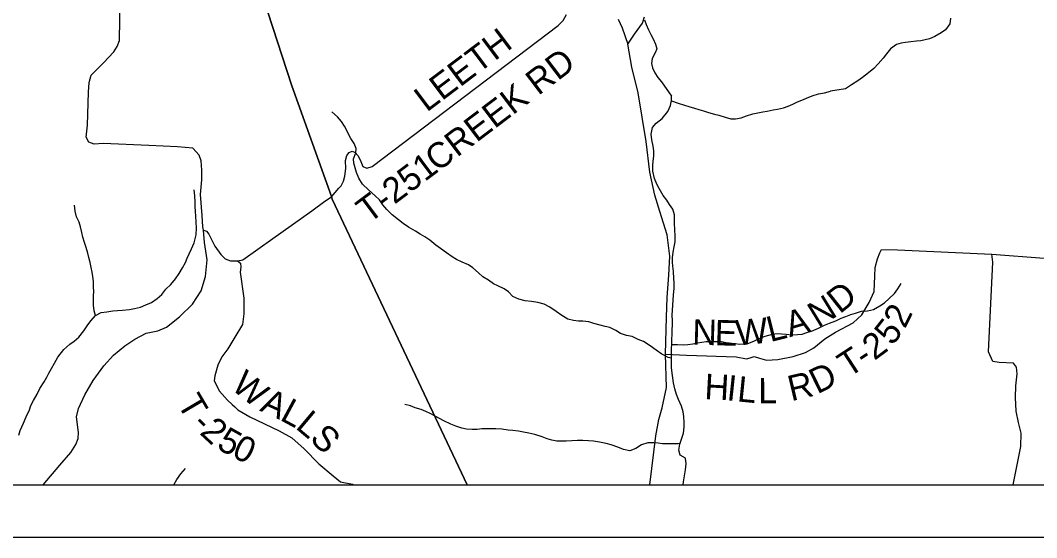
# Model space of a CAD drawing. Extents: x 0 to 34, y 0 to 22.
# Drawn here: x 3.486 to 5.759, y 13.882 to 15.038 of the extents above; entities that cross this region are included whole.
import ezdxf

# ---------------------------------------------------------------- set-up
doc = ezdxf.new("R2010")
doc.units = 0
for name, color, linetype in [('Default', 7, 'Continuous'), ('GM_X_County_Road', 7, 'Continuous'), ('GM_X_Minor_River', 7, 'Continuous'), ('GM_X_Township_Road', 7, 'Continuous'), ('GM_X_Township_Road_Text', 7, 'Continuous'), ('SH_Cut_Line', 7, 'Continuous')]:
    doc.layers.add(name, color=color, linetype=linetype)

msp = doc.modelspace()

# ---------------------------------------------------------------- linework, layer by layer
at = {"layer": 'Default'}
msp.add_lwpolyline([(9.087, 13.8822), (2.1062, 13.8822), (2.1062, 20.9054), (9.087, 20.9054)], close=True, dxfattribs=at)
for points in [[(2.2, 14), (4.485, 14), (4.1837, 14.6383), (4.1816, 14.6445), (4.0933, 14.8918), (3.8786, 15.5505)], [(3.8786, 15.5505), (4.0933, 14.8918), (4.1816, 14.6445), (4.1837, 14.6383), (4.485, 14), (9, 14)]]:
    msp.add_lwpolyline(points, dxfattribs=at)
at = {"layer": 'GM_X_County_Road'}
for points in [[(3.5373, 14), (3.5742, 14.0443), (3.5988, 14.0725), (3.6104, 14.0906), (3.6151, 14.1035), (3.616, 14.1168), (3.6118, 14.1522), (3.6165, 14.1711), (3.6301, 14.2014), (3.6487, 14.2335), (3.6725, 14.2659), (3.6944, 14.2899), (3.7196, 14.3106), (3.7425, 14.3259), (3.7677, 14.3389), (3.7939, 14.3443), (3.8133, 14.3524), (3.842, 14.3757), (3.8711, 14.4042), (3.8904, 14.434), (3.8998, 14.4658), (3.9036, 14.5027), (3.898, 14.5415), (3.8954, 14.5692), (3.8945, 14.5766), (3.8925, 14.6021), (3.8892, 14.6492), (3.8918, 14.6818), (3.8917, 14.7034), (3.8904, 14.7239), (3.886, 14.7365), (3.8718, 14.7523), (3.8374, 14.7553), (3.7732, 14.7581), (3.6715, 14.7625), (3.6511, 14.7616), (3.639, 14.7655), (3.6335, 14.7773), (3.636, 14.8035), (3.6387, 14.8775), (3.6401, 14.8991), (3.6444, 14.9154), (3.6719, 14.9432), (3.6949, 14.9672), (3.703, 14.9793), (3.708, 14.9932), (3.7113, 15.2305)], [(4.8447, 14.9846), (4.8597, 15.0073), (4.877, 15.0317), (4.8821, 15.0461)], [(4.8935, 14), (4.9075, 14.1096), (4.9135, 14.146), (4.9214, 14.1722), (4.9309, 14.218), (4.9284, 14.2921), (4.931, 14.3746), (4.9323, 14.4187), (4.9362, 14.4684), (4.9385, 14.511), (4.9322, 14.5586), (4.916, 14.6112), (4.905, 14.6474), (4.8934, 14.6985), (4.8858, 14.767), (4.8675, 14.8762), (4.8533, 14.9334), (4.8447, 14.9846)], [(5.7059, 14), (5.7234, 14.0857), (5.7237, 14.1154), (5.7182, 14.1394), (5.7132, 14.1649), (5.7116, 14.1953), (5.7119, 14.2212), (5.7152, 14.2481), (5.7134, 14.2633), (5.7071, 14.2721), (5.6749, 14.2736), (5.6608, 14.2757), (5.6508, 14.2975), (5.6609, 14.498), (5.6585, 14.5159), (5.7755, 14.5066)]]:
    msp.add_lwpolyline(points, dxfattribs=at)
at = {"layer": 'GM_X_Minor_River'}
for points in [[(4.8815, 15.0392), (4.8857, 15.0285), (4.891, 15.0167), (4.8959, 15.0065), (4.9008, 14.9966), (4.9065, 14.9844), (4.9096, 14.9745), (4.9058, 14.965), (4.8989, 14.9529), (4.8974, 14.9418), (4.8997, 14.9316), (4.905, 14.9205), (4.9118, 14.9106), (4.9198, 14.9004), (4.9424, 14.8688)], [(5.5661, 15.0429), (5.5646, 15.0299), (5.5547, 15.0166), (5.5449, 15.0098), (5.5308, 15.0018), (5.5191, 14.9969), (5.5096, 14.9942), (5.4997, 14.9919), (5.4899, 14.9912), (5.477, 14.9896), (5.4656, 14.9885), (5.4557, 14.9866), (5.4451, 14.9836), (5.4315, 14.9741), (5.4231, 14.9634), (5.4151, 14.9535), (5.4041, 14.9406), (5.3943, 14.9307), (5.3825, 14.9205), (5.3692, 14.9102), (5.359, 14.903), (5.3446, 14.8935), (5.3313, 14.8847), (5.2978, 14.8798)], [(4.9493, 14.2147), (4.9463, 14.2283), (4.9448, 14.239), (4.9433, 14.25), (4.9422, 14.2621), (4.9424, 14.302), (4.9428, 14.3164), (4.9432, 14.3259), (4.9433, 14.3362), (4.944, 14.3468), (4.9445, 14.3574), (4.9441, 14.3669), (4.9438, 14.3791), (4.9442, 14.3908), (4.945, 14.4015), (4.9466, 14.4242), (4.9481, 14.4398), (4.9482, 14.4512), (4.9475, 14.4614), (4.9464, 14.4766), (4.9449, 14.4884), (4.9442, 14.4979), (4.9442, 14.5077), (4.9458, 14.5203), (4.9484, 14.532), (4.9504, 14.5434), (4.9504, 14.5559), (4.9497, 14.5704), (4.9486, 14.584), (4.9487, 14.6034), (4.9453, 14.6163), (4.9378, 14.6262), (4.9314, 14.6361), (4.9235, 14.6468), (4.9144, 14.662), (4.9096, 14.6719), (4.9043, 14.6844), (4.9006, 14.7007), (4.9002, 14.7133), (4.9014, 14.7231), (4.9026, 14.7345), (4.9026, 14.7463), (4.9011, 14.7565), (4.8985, 14.771), (4.8967, 14.7835), (4.8998, 14.7987), (4.9077, 14.8085), (4.921, 14.8187), (4.9336, 14.8346), (4.94, 14.8479), (4.942, 14.8589), (4.9424, 14.8688)], [(4.9418, 14.858), (4.9571, 14.8528), (4.9711, 14.8482), (4.9809, 14.8451), (4.9938, 14.8416), (5.0036, 14.8386), (5.0134, 14.8359), (5.0252, 14.8324), (5.038, 14.8282), (5.0478, 14.8259), (5.0622, 14.8213), (5.0751, 14.8182), (5.0853, 14.8178), (5.0982, 14.8204), (5.1095, 14.8246), (5.1243, 14.8291), (5.1349, 14.8313), (5.1463, 14.8336), (5.1561, 14.835), (5.1694, 14.8377), (5.1792, 14.8395), (5.1925, 14.8425), (5.2031, 14.8459), (5.2133, 14.8504), (5.2239, 14.8561), (5.2338, 14.8598), (5.244, 14.8644), (5.2569, 14.8693), (5.2709, 14.8738), (5.2846, 14.876), (5.2978, 14.8798)], [(4.9423, 14.2834), (4.9348, 14.2849), (4.9204, 14.2918), (4.9079, 14.301), (4.8943, 14.3109), (4.8792, 14.3204), (4.8675, 14.325), (4.8539, 14.3319), (4.8414, 14.3338), (4.8282, 14.3381), (4.8176, 14.3449), (4.804, 14.3518), (4.7938, 14.3541), (4.7825, 14.3572), (4.7688, 14.361), (4.7571, 14.3641), (4.7439, 14.3657), (4.734, 14.3661), (4.7234, 14.3673), (4.7102, 14.3707), (4.6966, 14.3787), (4.6845, 14.3871), (4.6698, 14.3974), (4.6577, 14.4035), (4.643, 14.4078), (4.629, 14.4101), (4.6153, 14.4113), (4.6006, 14.4147), (4.5874, 14.4212), (4.5776, 14.4311), (4.5677, 14.4384), (4.5541, 14.4449), (4.5439, 14.4495), (4.5326, 14.4571), (4.5201, 14.4647), (4.5103, 14.4742), (4.4983, 14.4853), (4.4884, 14.4918), (4.4741, 14.4975), (4.4612, 14.5033), (4.4514, 14.5094), (4.4389, 14.5185), (4.4254, 14.528), (4.4155, 14.5353), (4.402, 14.5467), (4.3906, 14.5544), (4.3804, 14.5601), (4.3695, 14.5666), (4.354, 14.5761), (4.3423, 14.5837), (4.3317, 14.5921), (4.3174, 14.6032), (4.3053, 14.6154), (4.297, 14.6256), (4.2895, 14.6367), (4.2797, 14.6458), (4.2646, 14.6595), (4.251, 14.6721), (4.2431, 14.6854), (4.2378, 14.6983), (4.2348, 14.7082), (4.2318, 14.7192), (4.2311, 14.7287), (4.2364, 14.742), (4.2372, 14.7519), (4.2327, 14.7625), (4.2248, 14.7739), (4.2113, 14.8013), (4.2041, 14.8116), (4.1951, 14.8226), (4.183, 14.8333)], [(3.4827, 14.1109), (3.4861, 14.1215), (3.4933, 14.1382), (3.4991, 14.1522), (3.5063, 14.1677), (3.5098, 14.1776), (3.5155, 14.189), (3.5235, 14.203), (3.5299, 14.2151), (3.5395, 14.2303), (3.5452, 14.2405), (3.5501, 14.25), (3.5558, 14.2598), (3.5623, 14.2723), (3.5699, 14.2852), (3.5832, 14.3023), (3.5969, 14.3147), (3.6067, 14.3212), (3.6166, 14.3299), (3.6284, 14.3439), (3.6371, 14.3575), (3.6447, 14.3673), (3.6539, 14.3787), (3.6671, 14.3851), (3.6793, 14.387), (3.6933, 14.3892), (3.7031, 14.3896), (3.7148, 14.3907), (3.73, 14.3918), (3.7417, 14.394), (3.7546, 14.3974), (3.7667, 14.4023), (3.7796, 14.4075), (3.7921, 14.4162), (3.8024, 14.4257), (3.8115, 14.4374), (3.8229, 14.448), (3.8332, 14.4601), (3.8415, 14.4722), (3.8484, 14.4851), (3.8552, 14.4973), (3.8591, 14.5067), (3.864, 14.5166), (3.8686, 14.5276), (3.8751, 14.5412), (3.8793, 14.5591), (3.8797, 14.5735), (3.879, 14.5868), (3.8787, 14.6001), (3.878, 14.6107), (3.8772, 14.6217), (3.8769, 14.632), (3.8762, 14.646), (3.8751, 14.6589)], [(3.6539, 14.3787), (3.6509, 14.3886), (3.6498, 14.4015), (3.6494, 14.411), (3.6499, 14.4228), (3.6503, 14.4322), (3.6499, 14.4417), (3.6496, 14.4546), (3.6485, 14.4653), (3.647, 14.4752), (3.6444, 14.4858), (3.6422, 14.4972), (3.6395, 14.5078), (3.6369, 14.5181), (3.6332, 14.5302), (3.6294, 14.5416), (3.6261, 14.5534), (3.6238, 14.5637), (3.6208, 14.5766), (3.6179, 14.5872), (3.6115, 14.599), (3.6085, 14.6119), (3.6074, 14.6248)], [(4.9427, 14.3136), (4.9557, 14.3137), (4.9689, 14.3129), (4.9788, 14.3136), (4.9897, 14.3155), (5, 14.3178), (5.0098, 14.3192), (5.02, 14.3203), (5.0321, 14.3207), (5.0537, 14.3206), (5.0643, 14.3183), (5.084, 14.316), (5.095, 14.3148), (5.1052, 14.3151), (5.115, 14.317), (5.1275, 14.3219), (5.1381, 14.3268), (5.1514, 14.3321), (5.1677, 14.3366), (5.1783, 14.338), (5.1885, 14.3376), (5.1987, 14.3368), (5.2108, 14.3357), (5.2241, 14.336), (5.2347, 14.3371), (5.2449, 14.3405), (5.2555, 14.3435), (5.2707, 14.3503), (5.284, 14.3567), (5.2957, 14.3612), (5.3094, 14.3669), (5.3215, 14.3725), (5.3317, 14.3763), (5.3431, 14.3808), (5.3537, 14.3838), (5.3673, 14.3879), (5.3806, 14.389), (5.3942, 14.392), (5.4083, 14.3999), (5.4185, 14.4071), (5.4291, 14.4162), (5.4409, 14.4279), (5.4481, 14.4378), (5.4557, 14.4503)], [(4.9684, 14), (4.969, 14.0069), (4.971, 14.0202), (4.9733, 14.0339), (4.9748, 14.0468), (4.9734, 14.0597), (4.9613, 14.0662), (4.9583, 14.078), (4.961, 14.0909), (4.9648, 14.1019), (4.969, 14.1155), (4.9706, 14.1296), (4.9702, 14.1394), (4.9699, 14.1527), (4.968, 14.163), (4.9643, 14.1759), (4.9579, 14.1911), (4.953, 14.2021), (4.9493, 14.2147)], [(4.9616, 14.0926), (4.9568, 14.092), (4.947, 14.0917), (4.9326, 14.0917), (4.9224, 14.0921), (4.9122, 14.0933), (4.9023, 14.0937), (4.8891, 14.0938), (4.8751, 14.0896), (4.8625, 14.0813), (4.8493, 14.0764), (4.8345, 14.0795), (4.822, 14.0841), (4.8073, 14.0895), (4.796, 14.0925), (4.7808, 14.0956), (4.7676, 14.0976), (4.7566, 14.0988), (4.7437, 14.0996), (4.7316, 14.0992), (4.7066, 14.0978), (4.6855, 14.0978), (4.6745, 14.0998), (4.6643, 14.1029), (4.6533, 14.1071), (4.6363, 14.1124), (4.6231, 14.1155), (4.6113, 14.1178), (4.6, 14.1198), (4.5875, 14.1217), (4.5769, 14.1225), (4.5625, 14.1244), (4.5493, 14.1256), (4.5281, 14.1257), (4.5183, 14.1253), (4.5077, 14.1242), (4.4967, 14.1239), (4.4834, 14.1247), (4.4732, 14.127), (4.46, 14.1316), (4.4486, 14.1358), (4.4331, 14.1431), (4.4233, 14.1481), (4.4135, 14.1538), (4.4025, 14.1599), (4.3927, 14.1637), (4.3821, 14.1683), (4.3693, 14.1722), (4.3587, 14.1764), (4.3458, 14.1794)], [(3.829, 14), (3.8362, 14.0122), (3.845, 14.025), (3.8556, 14.0368)]]:
    msp.add_lwpolyline(points, dxfattribs=at)
at = {"layer": 'GM_X_Township_Road'}
for points in [[(4.1673, 14.6336), (4.1818, 14.6439), (4.1985, 14.6627), (4.2037, 14.6684), (4.2085, 14.6787), (4.2119, 14.6895), (4.2136, 14.7066), (4.213, 14.7245), (4.2162, 14.7359), (4.2213, 14.7428), (4.2281, 14.7453), (4.235, 14.743), (4.2407, 14.7362), (4.2458, 14.726), (4.2521, 14.7117), (4.2609, 14.7077), (4.2732, 14.7114), (4.6889, 15.0261), (4.7, 15.0374), (4.7077, 15.051)], [(4.8232, 15.0402), (4.8321, 15.0211), (4.8447, 14.9846)], [(3.8954, 14.5692), (3.9025, 14.567), (3.9079, 14.5604), (3.9207, 14.5336), (3.9344, 14.5148), (3.9444, 14.5054), (3.9558, 14.5006), (3.9649, 14.5003), (3.9717, 14.5003), (3.9834, 14.5026), (4.0509, 14.5502), (4.1376, 14.6123), (4.1673, 14.6336)], [(4.9284, 14.2921), (4.9758, 14.29), (5.0868, 14.2861), (5.1099, 14.282), (5.1179, 14.2842), (5.127, 14.2868), (5.1391, 14.2832), (5.1546, 14.2788), (5.18, 14.2804), (5.2142, 14.2873), (5.2415, 14.2957), (5.2606, 14.3065), (5.2851, 14.3264), (5.3091, 14.3413), (5.3484, 14.3625), (5.3679, 14.3798), (5.3845, 14.4073), (5.395, 14.4323), (5.3965, 14.4661), (5.3978, 14.4855), (5.4026, 14.5048), (5.408, 14.5184), (5.4119, 14.526), (5.4475, 14.5256), (5.6585, 14.5159)], [(3.9717, 14.5003), (3.9786, 14.4952), (3.9791, 14.4864), (3.978, 14.4752), (3.986, 14.4171), (3.9857, 14.382), (3.9832, 14.3581), (3.9658, 14.3298), (3.95, 14.3037), (3.9365, 14.286), (3.928, 14.2679), (3.9213, 14.244), (3.9196, 14.2326), (3.9312, 14.2097), (3.9495, 14.1897), (3.9597, 14.18)], [(3.9597, 14.18), (3.9655, 14.1744), (3.9724, 14.1678), (3.9995, 14.1523), (4.0651, 14.1211), (4.0934, 14.1056), (4.1208, 14.0806), (4.1534, 14.0475), (4.1857, 14.0201), (4.2018, 14.0066), (4.2291, 14.0018), (4.2317, 14)]]:
    msp.add_lwpolyline(points, dxfattribs=at)
at = {"layer": 'SH_Cut_Line'}
msp.add_lwpolyline([(2.2, 19.4329), (2.2, 14), (9, 14), (9, 18.8941), (8.8762, 18.9027), (8.0305, 18.9725), (6.8442, 19.0679), (6.226, 19.1161), (5.8337, 19.1499), (5.3224, 19.1939), (5.1554, 19.2083), (4.831, 19.2363), (4.7641, 19.2419), (3.1893, 19.3592), (2.7961, 19.3885)], close=True, dxfattribs=at)

# ---------------------------------------------------------------- texts
at = {"layer": 'GM_X_Township_Road_Text'}
for s, height, rotation, p in [('LEETH', 0.05682, 36.9998, (4.3948, 14.8316)), ('CREEK RD', 0.05682, 37.1772, (4.4187, 14.6976)), ('T-251', 0.05682, 36.8138, (4.2652, 14.5828)), ('D', 0.0568, 38.4069, (5.3184, 14.3808)), ('N', 0.0568, 31.4518, (5.2696, 14.3504)), ('A', 0.0568, 16.1292, (5.2064, 14.3298)), ('2', 0.0568, 63.6636, (5.4642, 14.3475)), ('N', 0.0568, 358.295, (4.988, 14.3136)), ('E', 0.0568, 358.4899, (5.0382, 14.3121)), ('W', 0.0568, 5.359, (5.0882, 14.3112)), ('L', 0.0568, 13.9743, (5.1629, 14.3189)), ('5', 0.0568, 51.828, (5.4358, 14.3092)), ('2', 0.0568, 36.6815, (5.396, 14.2769)), ('T', 0.0568, 33.0589, (5.3378, 14.2385)), ('-', 0.0568, 33.6455, (5.3739, 14.2621)), ('W', 0.0568, 321.0956, (3.9552, 14.2159)), ('R', 0.0568, 13.3386, (5.2099, 14.1868)), ('D', 0.0568, 26.0645, (5.268, 14.2021)), ('H', 0.0568, 356.9204, (5.0149, 14.192)), ('I', 0.0568, 353.9236, (5.0641, 14.1894)), ('L', 0.0568, 354.2744, (5.0877, 14.1869)), ('L', 0.0568, 0.1741, (5.1362, 14.1824)), ('T', 0.0568, 300.4875, (3.8356, 14.182)), ('A', 0.0568, 335.6399, (4.0198, 14.1663)), ('L', 0.0568, 331.7155, (4.0644, 14.1462)), ('L', 0.0568, 319.9914, (4.0993, 14.1278)), ('-', 0.0568, 315.9998, (3.8675, 14.1322)), ('2', 0.0568, 317.1715, (3.8852, 14.1152)), ('5', 0.0568, 330.716, (3.9227, 14.0828)), ('S', 0.0568, 315.588, (4.131, 14.1012)), ('0', 0.0568, 334.1481, (3.9565, 14.0639))]:
    msp.add_text(s, height=height, rotation=rotation, dxfattribs=at).set_placement(p)

doc.saveas('drawing.dxf')
